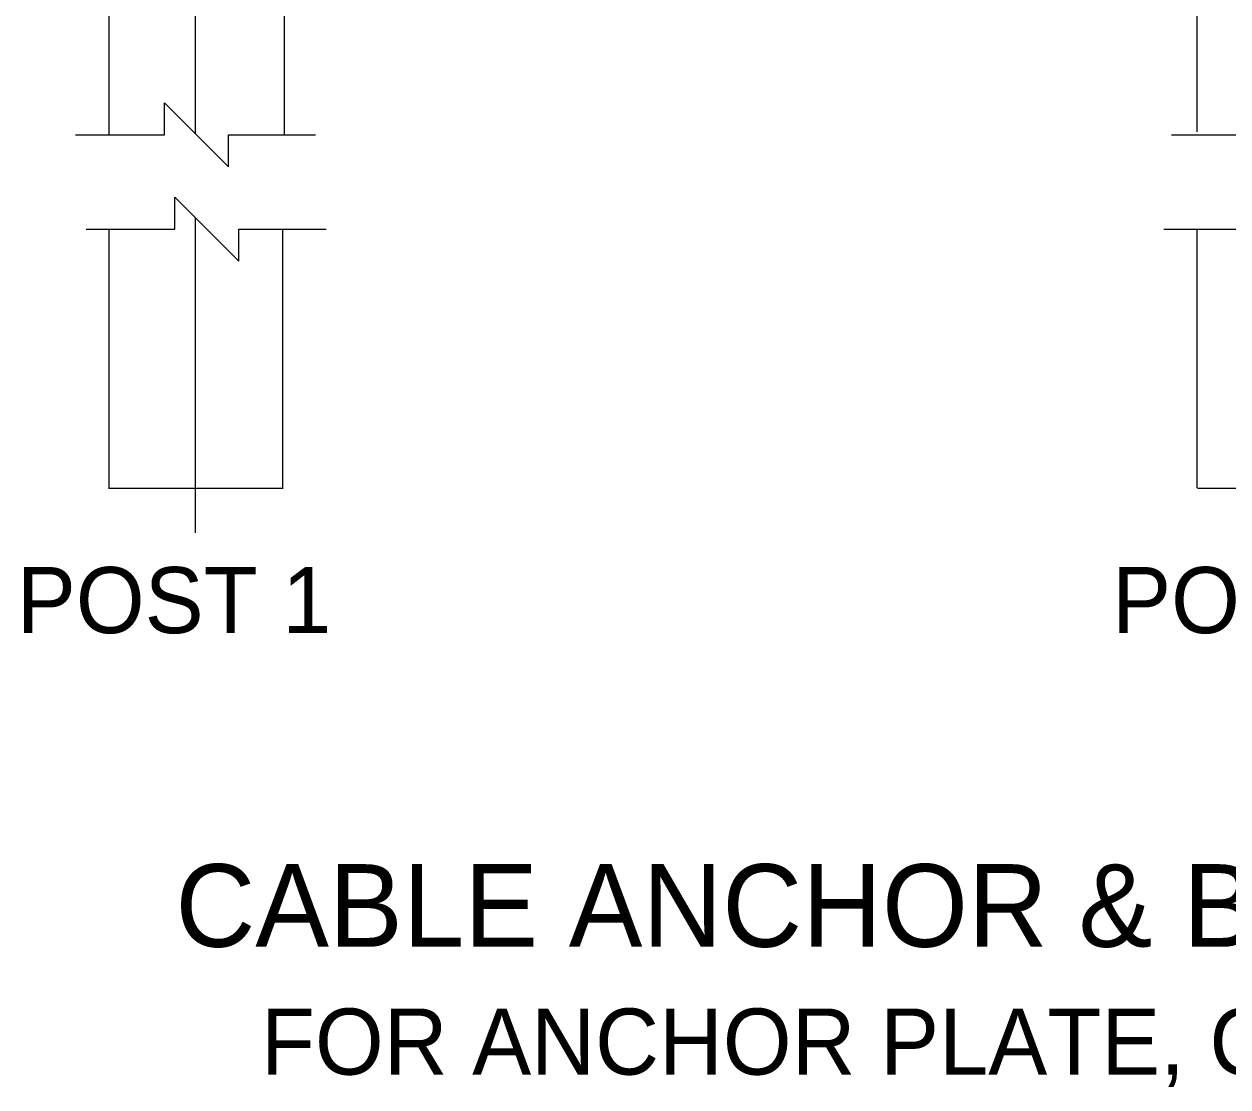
# Model space of a CAD drawing. Extents: x 1312564.2 to 1312581.5, y 1207298.4 to 1207352.6.
# Drawn here: x 1312577.508 to 1312578.965, y 1207334.48 to 1207335.767 of the extents above; entities that cross this region are included whole.
import ezdxf

# ---------------------------------------------------------------- set-up
doc = ezdxf.new("R2010")
doc.units = 0
for name, color, linetype in [('Level 15', 7, 'Continuous'), ('Level 20', 7, 'Continuous'), ('Level 3', 7, 'Continuous')]:
    doc.layers.add(name, color=color, linetype=linetype)

msp = doc.modelspace()

# ---------------------------------------------------------------- linework, layer by layer
at = {"layer": 'Level 15'}
for p, q in [((1312577.7146, 1207337.1794), (1312577.7146, 1207335.6344)), ((1312577.7146, 1207335.5329), (1312577.7146, 1207335.1511))]:
    msp.add_line(p, q, dxfattribs=at)
for points in [[(1312577.57, 1207335.6329), (1312577.6774, 1207335.6329), (1312577.6774, 1207335.6716), (1312577.7549, 1207335.5941), (1312577.7549, 1207335.6329), (1312577.8604, 1207335.6329)], [(1312578.8969, 1207335.6329), (1312579, 1207335.6329), (1312579, 1207335.6716), (1312579.0775, 1207335.5941), (1312579.0775, 1207335.6329), (1312579.1807, 1207335.6329)], [(1312577.5827, 1207335.5187), (1312577.6901, 1207335.5187), (1312577.6901, 1207335.5574), (1312577.7676, 1207335.4799), (1312577.7676, 1207335.5187), (1312577.8731, 1207335.5187)], [(1312578.8873, 1207335.5187), (1312578.9904, 1207335.5187), (1312578.9904, 1207335.5574), (1312579.0679, 1207335.4799), (1312579.0679, 1207335.5187), (1312579.1711, 1207335.5187)]]:
    msp.add_lwpolyline(points, dxfattribs=at)
at = {"layer": 'Level 3'}
for p, q in [((1312577.6101, 1207337.1369), (1312577.6101, 1207335.6329)), ((1312577.8223, 1207337.1369), (1312577.8223, 1207335.6329)), ((1312578.9273, 1207337.1369), (1312578.9273, 1207335.6367)), ((1312577.6101, 1207335.5187), (1312577.6101, 1207335.2054)), ((1312577.8203, 1207335.5187), (1312577.8203, 1207335.2054)), ((1312578.9273, 1207335.5187), (1312578.9273, 1207335.2054))]:
    msp.add_line(p, q, dxfattribs=at)
for points in [[(1312577.6098, 1207335.2051), (1312577.8214, 1207335.2051)], [(1312578.9282, 1207335.2051), (1312579.1313, 1207335.2051)]]:
    msp.add_lwpolyline(points, dxfattribs=at)

# ---------------------------------------------------------------- texts
at = {"layer": 'Level 20'}
for s, height, p in [('POST 1', 0.08008, (1312577.4988, 1207335.0296)), ('POST 2', 0.08008, (1312578.8248, 1207335.0296)), ('CABLE ANCHOR & BRACKET ASSEMBLY', 0.100096, (1312577.6908, 1207334.6498)), ('FOR ANCHOR PLATE, CABLE BEARING PLATE, AND ', 0.080077, (1312577.7943, 1207334.495))]:
    msp.add_text(s, height=height, dxfattribs=at).set_placement(p)

doc.saveas('drawing.dxf')
